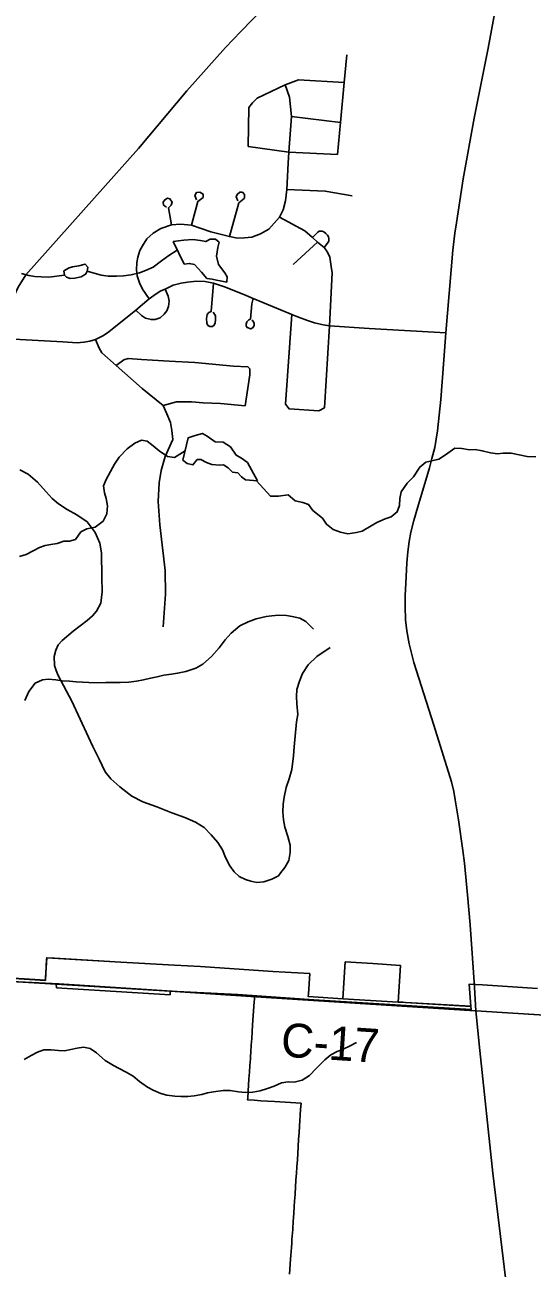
# Model space of a CAD drawing. Extents: x 208586767.6 to 208586821.4, y -134301046.9 to -134301022.9.
# Drawn here: x 208586782.765 to 208586783.617, y -134301027.656 to -134301025.568 of the extents above; entities that cross this region are included whole.
import ezdxf

# ---------------------------------------------------------------- set-up
doc = ezdxf.new("R2010")
doc.units = 0
for name, color, linetype in [('GM_X_City_Street', 7, 'Continuous'), ('GM_X_Corporation', 7, 'Continuous'), ('GM_X_County_Road', 7, 'Continuous'), ('GM_X_County_Road_Text', 7, 'Continuous'), ('GM_X_Minor_Lake', 7, 'Continuous'), ('GM_X_Minor_River', 7, 'Continuous'), ('GM_X_US_Route', 7, 'Continuous')]:
    doc.layers.add(name, color=color, linetype=linetype)

msp = doc.modelspace()

# ---------------------------------------------------------------- linework, layer by layer
at = {"layer": 'GM_X_City_Street'}
for p, q in [((208586783.2128, -134301025.7214), (208586783.295, -134301025.7314)), ((208586783.2155, -134301025.9703), (208586783.2563, -134301025.9327)), ((208586783.2025, -134301026.2049), (208586783.2129, -134301026.0539)), ((208586783.2679, -134301026.2108), (208586783.2764, -134301026.0732))]:
    msp.add_line(p, q, dxfattribs=at)
for points in [[(208586783.2896, -134301025.7855), (208586783.295, -134301025.7314), (208586783.3013, -134301025.6642), (208586783.3053, -134301025.618)], [(208586782.9736, -134301026.0279), (208586782.9624, -134301026.0116), (208586782.9571, -134301026.0011), (208586782.9532, -134301025.9889), (208586782.9522, -134301025.979), (208586782.9527, -134301025.967), (208586782.9545, -134301025.9576), (208586782.9581, -134301025.9466), (208586782.9622, -134301025.9385), (208586782.9698, -134301025.9272), (208586782.98, -134301025.9176), (208586782.9932, -134301025.9094), (208586783.0111, -134301025.9036), (208586783.0261, -134301025.9025), (208586783.0447, -134301025.9043), (208586783.077, -134301025.915), (208586783.1084, -134301025.9232), (208586783.1221, -134301025.926), (208586783.1336, -134301025.9255), (208586783.1461, -134301025.9242), (208586783.1603, -134301025.9188), (208586783.1746, -134301025.9107), (208586783.1927, -134301025.8908), (208586783.1988, -134301025.8783), (208586783.2026, -134301025.8631), (208586783.2049, -134301025.8442), (208586783.2069, -134301025.7999), (208586783.2082, -134301025.7816), (208586783.2128, -134301025.7214), (208586783.209, -134301025.6889), (208586783.2022, -134301025.6683)], [(208586783.1473, -134301025.6984), (208586783.1547, -134301025.6905), (208586783.2022, -134301025.6683), (208586783.2243, -134301025.6602), (208586783.3013, -134301025.6642)], [(208586783.1398, -134301025.7721), (208586783.141, -134301025.7064), (208586783.1473, -134301025.6984)], [(208586783.1398, -134301025.7721), (208586783.2082, -134301025.7816), (208586783.2896, -134301025.7855)], [(208586783.2049, -134301025.8442), (208586783.2693, -134301025.8469), (208586783.3144, -134301025.8548)], [(208586783.0111, -134301025.9036), (208586783.0062, -134301025.875), (208586783.0106, -134301025.8704), (208586783.0123, -134301025.8654), (208586783.0085, -134301025.8597), (208586783.0044, -134301025.8587), (208586782.9996, -134301025.8613), (208586782.9971, -134301025.8656), (208586782.9976, -134301025.8704), (208586783.0029, -134301025.874)], [(208586783.0447, -134301025.9043), (208586783.0554, -134301025.8641), (208586783.064, -134301025.8575), (208586783.064, -134301025.8519), (208586783.0587, -134301025.8485), (208586783.0531, -134301025.849), (208586783.0503, -134301025.8544), (208586783.0528, -134301025.8615)], [(208586783.1084, -134301025.9232), (208586783.1242, -134301025.8666), (208586783.1298, -134301025.862), (208586783.1338, -134301025.8585), (208586783.1336, -134301025.8524), (208586783.1303, -134301025.8488), (208586783.1257, -134301025.8485), (208586783.1211, -134301025.8524), (208586783.1196, -134301025.8564), (208586783.1226, -134301025.8631)], [(208586783.2764, -134301026.0732), (208586783.2811, -134301025.9841), (208586783.2794, -134301025.9736), (208586783.2767, -134301025.958), (208586783.2736, -134301025.9504), (208586783.2707, -134301025.9462), (208586783.2672, -134301025.9415), (208586783.2563, -134301025.9327), (208586783.2478, -134301025.925), (208586783.2348, -134301025.9134), (208586783.1927, -134301025.8908)], [(208586783.2672, -134301025.9415), (208586783.2745, -134301025.9323), (208586783.2751, -134301025.9302), (208586783.2754, -134301025.9283), (208586783.2754, -134301025.9265), (208586783.2747, -134301025.9235), (208586783.2731, -134301025.9207), (208586783.2703, -134301025.9179), (208586783.267, -134301025.9155), (208586783.2639, -134301025.9142), (208586783.2615, -134301025.9141), (208586783.2592, -134301025.9142), (208586783.2567, -134301025.9159), (208586783.2478, -134301025.925)], [(208586782.8835, -134301026.0961), (208586782.897, -134301026.0892), (208586782.9057, -134301026.0831), (208586782.9512, -134301026.0467), (208586782.9736, -134301026.0279), (208586782.9852, -134301026.0191), (208586782.9932, -134301026.0144), (208586783.0006, -134301026.0113), (208586783.0141, -134301026.005), (208586783.0271, -134301026.0013), (208586783.0379, -134301025.9996), (208586783.053, -134301025.9983), (208586783.0676, -134301025.9989), (208586783.0814, -134301026.0015), (208586783.1019, -134301026.0082), (208586783.1362, -134301026.0219), (208586783.1483, -134301026.0273), (208586783.2129, -134301026.0539), (208586783.2244, -134301026.0587), (208586783.2396, -134301026.0644), (208586783.251, -134301026.0682), (208586783.2659, -134301026.0712), (208586783.2764, -134301026.0732), (208586783.343, -134301026.0776), (208586783.4716, -134301026.0849)], [(208586782.9512, -134301026.0467), (208586782.9608, -134301026.0559), (208586782.9676, -134301026.0602), (208586782.9767, -134301026.0625), (208586782.9837, -134301026.0625), (208586782.9918, -134301026.0594), (208586782.999, -134301026.0537), (208586783.0034, -134301026.048), (208586783.0062, -134301026.0406), (208586783.007, -134301026.0318), (208586783.0052, -134301026.0234), (208586783.0006, -134301026.0113)], [(208586783.0809, -134301026.0504), (208586783.0835, -134301026.0533), (208586783.0848, -134301026.0565), (208586783.085, -134301026.0628), (208586783.0842, -134301026.0679), (208586783.0829, -134301026.072), (208586783.0797, -134301026.0741), (208586783.0756, -134301026.0741), (208586783.0722, -134301026.0723), (208586783.0703, -134301026.0688), (208586783.0699, -134301026.0606), (208586783.0708, -134301026.0541), (208586783.074, -134301026.0506), (208586783.0779, -134301026.049), (208586783.0814, -134301026.0015)], [(208586783.1458, -134301026.0634), (208586783.1483, -134301026.0655), (208586783.1501, -134301026.069), (208586783.1501, -134301026.072), (208586783.1482, -134301026.076), (208586783.1441, -134301026.0783), (208586783.138, -134301026.0761), (208586783.1364, -134301026.0733), (208586783.1364, -134301026.0701), (208586783.1378, -134301026.0663), (208586783.1409, -134301026.0633), (208586783.1438, -134301026.0618), (208586783.1457, -134301026.0361), (208586783.1483, -134301026.0273)], [(208586782.7253, -134301026.0943), (208586782.8284, -134301026.0999), (208586782.8524, -134301026.1015), (208586782.8641, -134301026.1007), (208586782.874, -134301026.0987), (208586782.8835, -134301026.0961)], [(208586782.997, -134301026.5787), (208586783.0009, -134301026.524), (208586783.0002, -134301026.484), (208586782.9913, -134301026.4074), (208586782.9888, -134301026.3679), (208586782.9904, -134301026.3365), (208586782.9939, -134301026.3158), (208586783.0002, -134301026.2923), (208586783.0133, -134301026.264), (208586783.0118, -134301026.249), (208586783.0092, -134301026.2353), (208586783.0035, -134301026.221), (208586782.9973, -134301026.2071), (208586782.962, -134301026.1784), (208586782.9181, -134301026.14), (208586782.8942, -134301026.1186), (208586782.8893, -134301026.1108), (208586782.8835, -134301026.0961)], [(208586782.9181, -134301026.14), (208586782.931, -134301026.1302), (208586782.9382, -134301026.1281), (208586782.9605, -134301026.1294), (208586782.9792, -134301026.1305), (208586783.0072, -134301026.1323), (208586783.05, -134301026.1349), (208586783.1154, -134301026.1406), (208586783.1393, -134301026.1419), (208586783.1426, -134301026.1456), (208586783.1424, -134301026.1554), (208586783.1346, -134301026.2076)], [(208586782.9973, -134301026.2071), (208586783.0194, -134301026.2006), (208586783.0446, -134301026.2008), (208586783.064, -134301026.2027), (208586783.0931, -134301026.2037), (208586783.1346, -134301026.2076)], [(208586783.2025, -134301026.2049), (208586783.2084, -134301026.2125), (208586783.2586, -134301026.216), (208586783.2679, -134301026.2108)], [(208586783.2774, -134301026.6136), (208586783.2553, -134301026.6286), (208586783.2408, -134301026.6425), (208586783.231, -134301026.6569), (208586783.2258, -134301026.6698), (208586783.2218, -134301026.6839), (208586783.2209, -134301026.6956), (208586783.2218, -134301026.7082), (208586783.2233, -134301026.726), (208586783.2212, -134301026.7383), (208586783.2172, -134301026.7803), (208586783.216, -134301026.7951), (208586783.2129, -134301026.8184), (208586783.2089, -134301026.834), (208586783.2037, -134301026.8482), (208586783.2003, -134301026.8648), (208586783.1985, -134301026.8764), (208586783.1978, -134301026.8896), (208586783.1991, -134301026.9028), (208586783.2015, -134301026.9148), (208586783.2064, -134301026.9305), (208586783.2104, -134301026.9452), (208586783.2104, -134301026.9578), (208586783.208, -134301026.971), (208586783.2015, -134301026.983), (208586783.1945, -134301026.9912), (208586783.1905, -134301026.9968), (208586783.1794, -134301027.0026), (208586783.1662, -134301027.0069), (208586783.1545, -134301027.0081), (208586783.1441, -134301027.006), (208586783.1352, -134301027.0032), (208586783.1245, -134301026.998), (208586783.1165, -134301026.99), (208586783.1091, -134301026.9802), (208586783.102, -134301026.9658), (208586783.0968, -134301026.9532), (208586783.0888, -134301026.9406), (208586783.0778, -134301026.928), (208586783.0661, -134301026.9157), (208586783.0511, -134301026.9065), (208586783.0333, -134301026.8988), (208586783.0118, -134301026.8912), (208586782.9866, -134301026.8807), (208586782.963, -134301026.8724), (208586782.9442, -134301026.8632), (208586782.9243, -134301026.8476), (208586782.9089, -134301026.8337), (208586782.8994, -134301026.8221), (208586782.8896, -134301026.8006), (208586782.8788, -134301026.7794), (208586782.8718, -134301026.764), (208586782.8438, -134301026.7033), (208586782.8208, -134301026.6606), (208586782.8171, -134301026.652), (208586782.8144, -134301026.6434), (208586782.814, -134301026.6286), (208586782.8168, -134301026.6176), (208586782.8208, -134301026.609), (208586782.8276, -134301026.6013), (208586782.846, -134301026.586), (208586782.8696, -134301026.5682), (208586782.8785, -134301026.5602), (208586782.8853, -134301026.5525), (208586782.8926, -134301026.539), (208586782.8945, -134301026.5196), (208586782.8942, -134301026.4954), (208586782.8933, -134301026.4546), (208586782.8905, -134301026.438), (208586782.8831, -134301026.4202), (208586782.8693, -134301026.4021), (208586782.8521, -134301026.3904), (208586782.8358, -134301026.3815), (208586782.8214, -134301026.3723), (208586782.8104, -134301026.3631), (208586782.8008, -134301026.352), (208586782.7858, -134301026.3357), (208586782.7704, -134301026.3222), (208586782.7563, -134301026.3152)]]:
    msp.add_lwpolyline(points, dxfattribs=at)
at = {"layer": 'GM_X_Corporation'}
for points in [[(208586781.2713, -134301027.0897), (208586781.6677, -134301027.1118), (208586781.7056, -134301027.1139), (208586781.7344, -134301027.1148), (208586781.8329, -134301027.1207), (208586781.8549, -134301027.122), (208586781.8736, -134301027.1231), (208586781.98, -134301027.1295), (208586782.1685, -134301027.1422), (208586782.6086, -134301027.1669), (208586782.6378, -134301027.1684), (208586782.648, -134301027.1691), (208586782.72, -134301027.1729), (208586782.8221, -134301027.178), (208586783.5221, -134301027.2233), (208586783.9036, -134301027.2474), (208586784.2616, -134301027.2694), (208586784.8283, -134301027.3051), (208586784.8283, -134301024.0407), (208586780.8686, -134301024.0407)], [(208586780.4561, -134301030.8407), (208586784.8283, -134301030.8407), (208586784.8283, -134301027.3051), (208586784.2616, -134301027.2694), (208586783.9036, -134301027.2474), (208586783.5221, -134301027.2233), (208586782.8221, -134301027.178), (208586782.72, -134301027.1729), (208586782.648, -134301027.1691), (208586782.6378, -134301027.1684), (208586782.6086, -134301027.1669), (208586782.1685, -134301027.1422), (208586781.98, -134301027.1295), (208586781.8736, -134301027.1231), (208586781.8549, -134301027.122), (208586781.8329, -134301027.1207), (208586781.7344, -134301027.1148), (208586781.7056, -134301027.1139), (208586781.6677, -134301027.1118), (208586781.2713, -134301027.0897)], [(208586782.6679, -134301027.1698), (208586782.8175, -134301027.1789), (208586783.0083, -134301027.1907), (208586783.1227, -134301027.1963), (208586783.25, -134301027.2049), (208586783.5142, -134301027.2214), (208586783.5138, -134301027.2157), (208586783.4038, -134301027.2095), (208586783.3995, -134301027.2092), (208586783.3916, -134301027.2087), (208586783.3453, -134301027.2059), (208586783.299, -134301027.2031), (208586783.2406, -134301027.1995), (208586783.2409, -134301027.1952), (208586783.2432, -134301027.1609), (208586783.181, -134301027.1573), (208586783.0596, -134301027.1489), (208586783.0161, -134301027.1469), (208586782.926, -134301027.1416), (208586782.8336, -134301027.1362), (208586782.8147, -134301027.1351), (208586782.8016, -134301027.1343), (208586782.8014, -134301027.1374), (208586782.7994, -134301027.1722), (208586782.7101, -134301027.1667)], [(208586782.7101, -134301027.167), (208586782.7994, -134301027.1724), (208586782.7997, -134301027.1683), (208586782.8016, -134301027.1343), (208586782.926, -134301027.1416), (208586783.0161, -134301027.1469), (208586783.0596, -134301027.1489), (208586783.181, -134301027.1573), (208586783.2432, -134301027.1609), (208586783.2409, -134301027.1952), (208586783.2406, -134301027.1995), (208586783.299, -134301027.2031), (208586783.3028, -134301027.1414), (208586783.3492, -134301027.1443), (208586783.3954, -134301027.1472), (208586783.3916, -134301027.2087), (208586783.3995, -134301027.2092), (208586783.4038, -134301027.2095), (208586783.5138, -134301027.216), (208586783.5112, -134301027.1786), (208586783.5332, -134301027.18), (208586783.6258, -134301027.1859)], [(208586783.2094, -134301027.6657), (208586783.2111, -134301027.6408), (208586783.2116, -134301027.6342), (208586783.2125, -134301027.6211), (208586783.213, -134301027.614), (208586783.2134, -134301027.6078), (208586783.2146, -134301027.5908), (208586783.2156, -134301027.5761), (208586783.2159, -134301027.5719), (208586783.2172, -134301027.553), (208586783.2179, -134301027.542), (208586783.2181, -134301027.5388), (208586783.2186, -134301027.5306), (208586783.2201, -134301027.508), (208586783.2205, -134301027.5017), (208586783.2209, -134301027.4966), (208586783.2216, -134301027.4853), (208586783.2224, -134301027.4739), (208586783.223, -134301027.4634), (208586783.2238, -134301027.4513), (208586783.2246, -134301027.4399), (208586783.2254, -134301027.4278), (208586783.2261, -134301027.4172), (208586783.2279, -134301027.3895), (208586783.2286, -134301027.3788), (208586783.2018, -134301027.3771), (208586783.1838, -134301027.376), (208586783.1725, -134301027.3752), (208586783.1611, -134301027.3745), (208586783.1498, -134301027.3738), (208586783.1388, -134301027.3731), (208586783.1391, -134301027.37), (208586783.1398, -134301027.3587), (208586783.1412, -134301027.3379), (208586783.1419, -134301027.3266), (208586783.1427, -134301027.3152), (208586783.1435, -134301027.3039), (208586783.1437, -134301027.3006), (208586783.1442, -134301027.2926), (208586783.145, -134301027.2812), (208586783.1457, -134301027.2699), (208586783.1465, -134301027.2586), (208586783.1472, -134301027.2472), (208586783.1498, -134301027.2084), (208586783.1502, -134301027.2037), (208586783.1505, -134301027.1982), (208586783.1227, -134301027.1963), (208586783.0091, -134301027.1907), (208586783.0088, -134301027.1966), (208586782.818, -134301027.1849), (208586782.8175, -134301027.1789), (208586782.6679, -134301027.1698)]]:
    msp.add_lwpolyline(points, dxfattribs=at)
at = {"layer": 'GM_X_County_Road'}
for p, q in [((208586783.0091, -134301027.1906), (208586783.1528, -134301027.1999)), ((208586783.1528, -134301027.1999), (208586783.512, -134301027.2231)), ((208586783.5223, -134301027.2238), (208586783.5201, -134301027.1843)), ((208586783.512, -134301027.2231), (208586783.5223, -134301027.2238)), ((208586783.5223, -134301027.2238), (208586783.837, -134301027.2437))]:
    msp.add_line(p, q, dxfattribs=at)
for points in [[(208586783.5201, -134301027.1843), (208586783.52, -134301027.1833), (208586783.5129, -134301027.0789), (208586783.5084, -134301027.0286), (208586783.5034, -134301026.9755), (208586783.5006, -134301026.9542), (208586783.4933, -134301026.903), (208586783.4875, -134301026.869), (208586783.4851, -134301026.8553), (208586783.4815, -134301026.8389), (208586783.4514, -134301026.7439), (208586783.418, -134301026.6385), (208586783.4101, -134301026.6069), (208586783.4062, -134301026.5856), (208586783.4043, -134301026.5667), (208586783.4034, -134301026.5447), (208586783.4036, -134301026.5258), (208586783.4045, -134301026.5051), (208586783.4064, -134301026.4714), (208586783.4077, -134301026.4525), (208586783.4103, -134301026.4355), (208586783.4129, -134301026.4198), (208586783.418, -134301026.4002), (208586783.4245, -134301026.3772), (208586783.4443, -134301026.3114), (208586783.4483, -134301026.2957), (208586783.4531, -134301026.2774), (208586783.4576, -134301026.2496), (208586783.4634, -134301026.197), (208586783.4686, -134301026.1301), (208586783.4716, -134301026.0849), (208586783.4838, -134301025.9462), (208586783.4871, -134301025.9174), (208586783.4899, -134301025.8999), (208586783.501, -134301025.826), (208586783.5195, -134301025.7242), (208586783.5428, -134301025.6066), (208586783.5653, -134301025.4855)], [(208586782.6708, -134301027.1708), (208586782.7202, -134301027.1734), (208586782.8141, -134301027.1782)], [(208586782.8141, -134301027.1782), (208586782.8223, -134301027.1786), (208586783.0091, -134301027.1906)], [(208586783.5826, -134301027.8014), (208586783.574, -134301027.6903), (208586783.5505, -134301027.4964), (208586783.5287, -134301027.2902), (208586783.5223, -134301027.2238)]]:
    msp.add_lwpolyline(points, dxfattribs=at)
at = {"layer": 'GM_X_Minor_Lake'}
for points in [[(208586783.0324, -134301025.9697), (208586783.0408, -134301025.9682), (208586783.0495, -134301025.9701), (208586783.0615, -134301025.9831), (208586783.0706, -134301025.9938), (208586783.0793, -134301025.9946), (208586783.0865, -134301025.9962), (208586783.0926, -134301025.9973), (208586783.1039, -134301025.9997), (208586783.1048, -134301025.9906), (208586783.1006, -134301025.9841), (208586783.0901, -134301025.97), (208586783.0868, -134301025.9563), (208586783.0891, -134301025.9415), (208586783.0911, -134301025.9328), (208586783.0847, -134301025.9275), (208586783.0759, -134301025.9278), (208586783.0687, -134301025.9315), (208586783.06, -134301025.93), (208586783.0471, -134301025.928), (208586783.0315, -134301025.929), (208586783.0137, -134301025.9312)], [(208586783.0137, -134301025.9312), (208586783.0324, -134301025.9697)], [(208586782.8311, -134301025.9882), (208586782.8345, -134301025.9916), (208586782.8406, -134301025.9936), (208586782.8486, -134301025.9928), (208586782.8592, -134301025.9906), (208586782.8668, -134301025.9865), (208586782.8695, -134301025.982), (208586782.8703, -134301025.9744), (208586782.8658, -134301025.9694), (208586782.8552, -134301025.9724), (208586782.8449, -134301025.9738), (208586782.8392, -134301025.9757), (208586782.8304, -134301025.981)], [(208586782.8304, -134301025.981), (208586782.8311, -134301025.9882)], [(208586783.1554, -134301026.3336), (208586783.1389, -134301026.3028), (208586783.1286, -134301026.2955), (208586783.1196, -134301026.2902), (208586783.1102, -134301026.2764), (208586783.0981, -134301026.2684), (208586783.0844, -134301026.2679), (208586783.0708, -134301026.2584), (208586783.0629, -134301026.2538), (208586783.0507, -134301026.2571), (208586783.0393, -134301026.2612), (208586783.03, -134301026.2987), (208586783.0375, -134301026.3041), (208586783.047, -134301026.3068), (208586783.0542, -134301026.2977), (208586783.0603, -134301026.2978), (208586783.0698, -134301026.3028), (208586783.0789, -134301026.3062), (208586783.0918, -134301026.3071), (208586783.0986, -134301026.3063), (208586783.1065, -134301026.3117), (208586783.1133, -134301026.3186), (208586783.1224, -134301026.3198), (208586783.1288, -134301026.3266), (208586783.1353, -134301026.3316)], [(208586783.1353, -134301026.3316), (208586783.1554, -134301026.3336)]]:
    msp.add_lwpolyline(points, dxfattribs=at)
at = {"layer": 'GM_X_Minor_River'}
for points in [[(208586782.8696, -134301025.9813), (208586782.893, -134301025.9878), (208586782.9048, -134301025.9898), (208586782.9188, -134301025.9899), (208586782.9302, -134301025.9892), (208586782.9431, -134301025.9877), (208586782.9572, -134301025.984), (208586782.9674, -134301025.9803), (208586782.9804, -134301025.9743), (208586782.9945, -134301025.9641), (208586783.0067, -134301025.9551), (208586783.0208, -134301025.9459)], [(208586782.7591, -134301025.9851), (208586782.7716, -134301025.9886), (208586782.7818, -134301025.9902), (208586782.792, -134301025.991), (208586782.8053, -134301025.9911), (208586782.8311, -134301025.9882)], [(208586782.923, -134301026.2935), (208586782.9367, -134301026.2799), (208586782.9493, -134301026.2702), (208586782.9607, -134301026.2653), (208586782.9702, -134301026.2669), (208586782.9804, -134301026.2745), (208586782.9906, -134301026.2833), (208586783.0042, -134301026.2925), (208586783.0163, -134301026.2945), (208586783.0338, -134301026.2832)], [(208586783.154, -134301026.3335), (208586783.1776, -134301026.3592), (208586783.1905, -134301026.3593), (208586783.2068, -134301026.3571), (208586783.2185, -134301026.367), (208586783.2314, -134301026.3698), (208586783.2413, -134301026.3732), (208586783.2484, -134301026.3832), (208586783.2646, -134301026.3962), (208586783.2714, -134301026.4064), (208586783.2827, -134301026.4149), (208586783.2949, -134301026.4195), (208586783.307, -134301026.4222), (208586783.3218, -134301026.42), (208586783.3313, -134301026.4178), (208586783.3465, -134301026.4088), (208586783.3561, -134301026.4032), (208586783.3698, -134301026.3975), (208586783.38, -134301026.3938), (208586783.3903, -134301026.3855), (208586783.3938, -134301026.3749), (208586783.3946, -134301026.3632), (208586783.3966, -134301026.3518), (208586783.4066, -134301026.3374), (208586783.4177, -134301026.3265), (208586783.4284, -134301026.3102), (208586783.4383, -134301026.3019), (208586783.4482, -134301026.3001), (208586783.46, -134301026.2971), (208586783.4714, -134301026.29), (208586783.487, -134301026.2783), (208586783.4988, -134301026.2791), (208586783.5113, -134301026.2811), (208586783.5208, -134301026.2808), (208586783.5329, -134301026.2828), (208586783.5466, -134301026.2863), (208586783.5587, -134301026.2878), (208586783.5682, -134301026.2871), (208586783.5815, -134301026.2868), (208586783.5951, -134301026.29), (208586783.6084, -134301026.2923), (208586783.6232, -134301026.2932)], [(208586782.7557, -134301026.4603), (208586782.7671, -134301026.4573), (208586782.7785, -134301026.4509), (208586782.7892, -134301026.4453), (208586782.7987, -134301026.442), (208586782.8086, -134301026.4401), (208586782.8188, -134301026.4387), (208586782.8302, -134301026.4349), (208586782.8397, -134301026.4346), (208586782.8496, -134301026.432), (208586782.8588, -134301026.4188), (208586782.8691, -134301026.4143), (208586782.8831, -134301026.411), (208586782.8961, -134301026.4012), (208586782.9022, -134301026.3891), (208586782.9035, -134301026.3754), (208586782.9016, -134301026.3632), (208586782.8987, -134301026.3537), (208586782.8969, -134301026.3416), (208586782.9011, -134301026.331), (208586782.9088, -134301026.3177), (208586782.9153, -134301026.3052), (208586782.923, -134301026.2935)], [(208586782.7648, -134301026.7021), (208586782.7717, -134301026.6874), (208586782.782, -134301026.6734), (208586782.7942, -134301026.6674), (208586782.8037, -134301026.6663), (208586782.8166, -134301026.6679), (208586782.8272, -134301026.6691), (208586782.8397, -134301026.6696), (208586782.8511, -134301026.6711), (208586782.8614, -134301026.6716), (208586782.872, -134301026.672), (208586782.8864, -134301026.6725), (208586782.9005, -134301026.6722), (208586782.9134, -134301026.6723), (208586782.9251, -134301026.672), (208586782.9392, -134301026.6713), (208586782.9521, -134301026.6698), (208586782.9642, -134301026.6676), (208586782.976, -134301026.6651), (208586782.987, -134301026.6625), (208586782.9981, -134301026.6599), (208586783.011, -134301026.6581), (208586783.0212, -134301026.6566), (208586783.0349, -134301026.6536), (208586783.0517, -134301026.648), (208586783.0638, -134301026.6413), (208586783.078, -134301026.6285), (208586783.0913, -134301026.6137), (208586783.1013, -134301026.6005), (208586783.1112, -134301026.5892), (208586783.1261, -134301026.5771), (208586783.1398, -134301026.5704), (208586783.1531, -134301026.5652), (208586783.1699, -134301026.5615), (208586783.1794, -134301026.56), (208586783.1907, -134301026.5593), (208586783.204, -134301026.5598), (208586783.2135, -134301026.561), (208586783.2264, -134301026.5641), (208586783.2366, -134301026.5694), (208586783.2498, -134301026.5824)], [(208586782.7636, -134301027.3052), (208586782.7754, -134301027.2985), (208586782.7861, -134301027.2928), (208586782.7964, -134301027.2891), (208586782.8089, -134301027.2888), (208586782.8214, -134301027.2904), (208586782.8316, -134301027.2905), (208586782.8525, -134301027.2864), (208586782.8632, -134301027.2846), (208586782.8746, -134301027.2869), (208586782.8851, -134301027.2942), (208586782.8999, -134301027.3068), (208586782.9135, -134301027.3156), (208586782.9233, -134301027.3202), (208586782.935, -134301027.3267), (208586782.9464, -134301027.3333), (208586782.9573, -134301027.3421), (208586782.9706, -134301027.3516), (208586782.9804, -134301027.357), (208586782.9933, -134301027.3624), (208586783.0031, -134301027.3651), (208586783.0164, -134301027.3667), (208586783.027, -134301027.3675), (208586783.0384, -134301027.3672), (208586783.0494, -134301027.3661)], [(208586783.0494, -134301027.3661), (208586783.0619, -134301027.3639), (208586783.0718, -134301027.3613), (208586783.0817, -134301027.3595), (208586783.098, -134301027.3573), (208586783.1094, -134301027.3574), (208586783.1238, -134301027.3594), (208586783.1348, -134301027.3606), (208586783.1474, -134301027.3599), (208586783.1599, -134301027.3577), (208586783.1725, -134301027.354), (208586783.1835, -134301027.3499), (208586783.196, -134301027.3446), (208586783.2071, -134301027.3428), (208586783.2169, -134301027.3432), (208586783.2306, -134301027.3399), (208586783.2428, -134301027.332), (208586783.2539, -134301027.3203), (208586783.2684, -134301027.306), (208586783.2787, -134301027.2977), (208586783.2894, -134301027.2921), (208586783.3004, -134301027.2872), (208586783.3099, -134301027.2831), (208586783.3217, -134301027.2767)]]:
    msp.add_lwpolyline(points, dxfattribs=at)
at = {"layer": 'GM_X_US_Route'}
msp.add_lwpolyline([(208586782.4853, -134301026.5325), (208586782.5012, -134301026.4973), (208586782.5143, -134301026.4659), (208586782.5486, -134301026.4088), (208586782.6056, -134301026.3226), (208586782.6341, -134301026.2817), (208586782.6793, -134301026.2103), (208586782.695, -134301026.1812), (208586782.7036, -134301026.1634), (208586782.7253, -134301026.0943), (208586782.7357, -134301026.0531), (208586782.7434, -134301026.0296), (208586782.7495, -134301026.0164), (208586782.7538, -134301026.0082), (208586782.7665, -134301025.9874), (208586782.9555, -134301025.7754), (208586783.0368, -134301025.6785), (208586783.1017, -134301025.6059), (208586783.1277, -134301025.5788), (208586783.1683, -134301025.5368), (208586783.2339, -134301025.4691), (208586783.2905, -134301025.4127), (208586783.3393, -134301025.3632)], dxfattribs=at)

# ---------------------------------------------------------------- texts
at = {"layer": 'GM_X_County_Road_Text'}
msp.add_text('C-17', height=0.05682, rotation=356.2322, dxfattribs=at).set_placement((208586783.1937, -134301027.3001))

doc.saveas('drawing.dxf')
